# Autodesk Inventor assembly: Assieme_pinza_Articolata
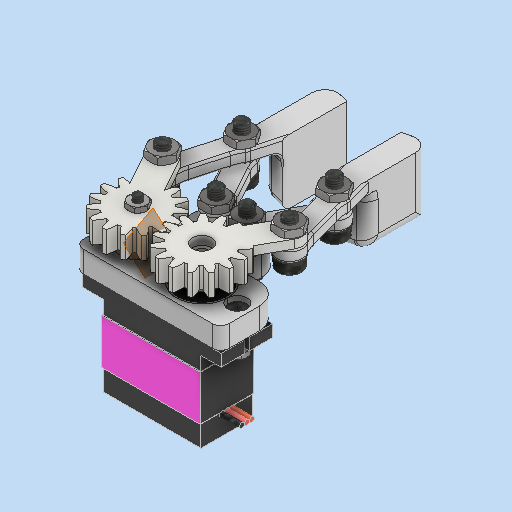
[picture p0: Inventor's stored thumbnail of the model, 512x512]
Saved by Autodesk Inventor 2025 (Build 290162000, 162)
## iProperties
Created: 2026-03
Part Number: Assieme_pinza_Articolata
Document SubType Name: Assembly
Designer: R5800u
Author: R5800u
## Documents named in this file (17)
- C:\Users\Ryzen5700u\Desktop\pinza articolata\Workgroups\NotInProject\Assieme_pinza_Articolata.iam
- C:\Users\Ryzen5700u\Desktop\pinza articolata\Workgroups\NotInProject\MG90_ldb.ipt
- C:\Users\Ryzen5700u\Desktop\pinza articolata\Workgroups\NotInProject\MG90S ARM.ipt
- C:\Users\Ryzen5700u\Desktop\pinza articolata\Workgroups\NotInProject\blocco_pinza_articolata.ipt
- C:\Users\Ryzen5700u\Desktop\pinza articolata\Workgroups\NotInProject\leva1.ipt
- C:\Users\Ryzen5700u\Desktop\pinza articolata\Workgroups\NotInProject\leva2.ipt
- C:\Users\Ryzen5700u\Desktop\pinza articolata\Workgroups\NotInProject\leva2b.ipt
- C:\Users\Ryzen5700u\Desktop\pinza articolata\Workgroups\NotInProject\Ingranaggio cilindrico21.ipt
- C:\Users\Ryzen5700u\Desktop\pinza articolata\Workgroups\NotInProject\Ingranaggio cilindrico12.ipt
- C:\Users\Ryzen5700u\Documents\Inventor\Content Center Files\R2025\it-IT\ISO 14580_2011(E)\ISO 14580 M3x8-4.8.ipt
- C:\Users\Ryzen5700u\Documents\Inventor\Content Center Files\R2025\it-IT\ISO 14580_2011(E)\ISO 14580 M3x12-4.8.ipt
- C:\Users\Ryzen5700u\Documents\Inventor\Content Center Files\R2025\it-IT\ISO 14580_2011(E)\ISO 14580 M3x10-4.8.ipt
- C:\Users\Ryzen5700u\Documents\Inventor\Content Center Files\R2025\it-IT\ISO 14580_2011(E)\ISO 14580 M2x12-4.8.ipt
- C:\Users\Ryzen5700u\Documents\Inventor\Content Center Files\R2025\it-IT\ISO 14580_2011(E)\ISO 14580 M2x6-4.8.ipt
- C:\Users\Ryzen5700u\Documents\Inventor\Content Center Files\R2025\it-IT\AS 1112 (4)\AS 1112 - M3(2).ipt
- C:\Users\Ryzen5700u\Documents\Inventor\Content Center Files\R2025\it-IT\AS 1112 (4)\AS 1112 - M2(2).ipt
- C:\Users\Ryzen5700u\Documents\Inventor\Content Center Files\R2025\it-IT\ISO 14580_2011(E)\ISO 14580 M2x8-4.8.ipt
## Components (30 placed, 16 different names)
1. MG90_ldb:1 — Rotazionale:1, Allineato:1, Rotazionale:15, Rotazionale:16, Rotazionale:18
2. blocco_pinza_articolata:1
3. MG90S ARM:1 — Rotazionale:1
4. leva1:1 — Rotazionale:2, Rotazionale:4, Simmetria:1, Rotazionale:8, Coincidente:12
5. leva1:2 — Rotazionale:3, Rotazionale:5, Simmetria:1, Rotazionale:10, Coincidente:14
6. leva2:1 — Rotazionale:4, Simmetria:2, Coincidente:1, Coincidente:4
7. leva2b:1 — Rotazionale:5, Simmetria:2, Coincidente:2, Rigido:2, Coincidente:8
8. Ingranaggio cilindrico2:1 — Rotazionale:7, Coincidente:2, Rotazione:1, Coincidente:10, Allineato:2
9. Ingranaggio cilindrico1:1 — Coincidente:1, Rotazione:1, Rotazionale:12, Coincidente:6, Coincidente:17, Allineato:2
10. Vite ISO 14580:2011(E) M3x8-4.8:1
11. Vite ISO 14580:2011(E) M3x10-4.8:1 — Rotazionale:8
12. Vite ISO 14580:2011(E) M3x12-4.8:1 — Rotazionale:9
13. Vite ISO 14580:2011(E) M3x12-4.8:2 — Rigido:1
14. Vite ISO 14580:2011(E) M3x8-4.8:2 — Rigido:2
15. Vite ISO 14580:2011(E) M3x10-4.8:2 — Rotazionale:10
16. Vite ISO 14580:2011(E) M2x12-4.8:1 — Rotazionale:11
17. Vite ISO 14580:2011(E) M2x6-4.8:1 — Rotazionale:12
18. AS 1112 (4) - Metrico M3:1 — Coincidente:4
19. AS 1112 (4) - Metrico M3:2 — Coincidente:6
20. AS 1112 (4) - Metrico M3:3 — Coincidente:8
21. AS 1112 (4) - Metrico M3:4 — Coincidente:10
22. AS 1112 (4) - Metrico M3:5 — Coincidente:12
23. AS 1112 (4) - Metrico M3:6 — Coincidente:14
24. AS 1112 (4) - Metrico M2:1 — Coincidente:16
25. Vite ISO 14580:2011(E) M2x8-4.8:1 — Rotazionale:13
26. Vite ISO 14580:2011(E) M2x8-4.8:2 — Rotazionale:14
27. AS 1112 (4) - Metrico M2:2 — Rotazionale:15
28. AS 1112 (4) - Metrico M2:3 — Rotazionale:16
29. Vite ISO 14580:2011(E) M2x8-4.8:3 — Rotazionale:17
30. AS 1112 (4) - Metrico M2:4 — Rotazionale:18
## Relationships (34: RevoluteJoint 17, Mate 10, Flush 2, Symmetry 2, WeldJoint 2, RelateRotation 1)
- Rotazionale:1 [RevoluteJoint]: MG90_ldb:1 ↔ MG90S ARM:1
- Allineato:1 [Flush]: MG90_ldb:1
- Rotazionale:2 [RevoluteJoint]: leva1:1
- Rotazionale:3 [RevoluteJoint]: leva1:2
- Rotazionale:4 [RevoluteJoint]: leva1:1 ↔ leva2:1
- Rotazionale:5 [RevoluteJoint]: leva1:2 ↔ leva2b:1
- Simmetria:1 [Symmetry]: leva1:1 ↔ leva1:2
- Simmetria:2 [Symmetry]: leva2:1 ↔ leva2b:1
- Coincidente:1 [Mate]: leva2:1 ↔ Ingranaggio cilindrico1:1
- Rotazionale:7 [RevoluteJoint]: Ingranaggio cilindrico2:1
- Coincidente:2 [Mate]: leva2b:1 ↔ Ingranaggio cilindrico2:1
- Rotazione:1 [RelateRotation]: Ingranaggio cilindrico2:1 ↔ Ingranaggio cilindrico1:1
- Rotazionale:8 [RevoluteJoint]: leva1:1 ↔ Vite ISO 14580:2011(E) M3x10-4.8:1
- Rotazionale:9 [RevoluteJoint]: Vite ISO 14580:2011(E) M3x12-4.8:1
- Rigido:1 [WeldJoint]: Vite ISO 14580:2011(E) M3x12-4.8:2
- Rigido:2 [WeldJoint]: leva2b:1 ↔ Vite ISO 14580:2011(E) M3x8-4.8:2
- Rotazionale:10 [RevoluteJoint]: leva1:2 ↔ Vite ISO 14580:2011(E) M3x10-4.8:2
- Rotazionale:11 [RevoluteJoint]: Vite ISO 14580:2011(E) M2x12-4.8:1
- Rotazionale:12 [RevoluteJoint]: Ingranaggio cilindrico1:1 ↔ Vite ISO 14580:2011(E) M2x6-4.8:1
- Coincidente:4 [Mate]: leva2:1 ↔ AS 1112 (4) - Metrico M3:1
- Coincidente:6 [Mate]: Ingranaggio cilindrico1:1 ↔ AS 1112 (4) - Metrico M3:2
- Coincidente:8 [Mate]: leva2b:1 ↔ AS 1112 (4) - Metrico M3:3
- Coincidente:10 [Mate]: Ingranaggio cilindrico2:1 ↔ AS 1112 (4) - Metrico M3:4
- Coincidente:12 [Mate]: leva1:1 ↔ AS 1112 (4) - Metrico M3:5
- Coincidente:14 [Mate]: leva1:2 ↔ AS 1112 (4) - Metrico M3:6
- Coincidente:16 [Mate]: AS 1112 (4) - Metrico M2:1
- Rotazionale:13 [RevoluteJoint]: Vite ISO 14580:2011(E) M2x8-4.8:1
- Rotazionale:14 [RevoluteJoint]: Vite ISO 14580:2011(E) M2x8-4.8:2
- Rotazionale:15 [RevoluteJoint]: MG90_ldb:1 ↔ AS 1112 (4) - Metrico M2:2
- Rotazionale:16 [RevoluteJoint]: MG90_ldb:1 ↔ AS 1112 (4) - Metrico M2:3
- Coincidente:17 [Mate]: Ingranaggio cilindrico1:1
- Allineato:2 [Flush]: Ingranaggio cilindrico2:1 ↔ Ingranaggio cilindrico1:1
- Rotazionale:17 [RevoluteJoint]: Vite ISO 14580:2011(E) M2x8-4.8:3
- Rotazionale:18 [RevoluteJoint]: MG90_ldb:1 ↔ AS 1112 (4) - Metrico M2:4
